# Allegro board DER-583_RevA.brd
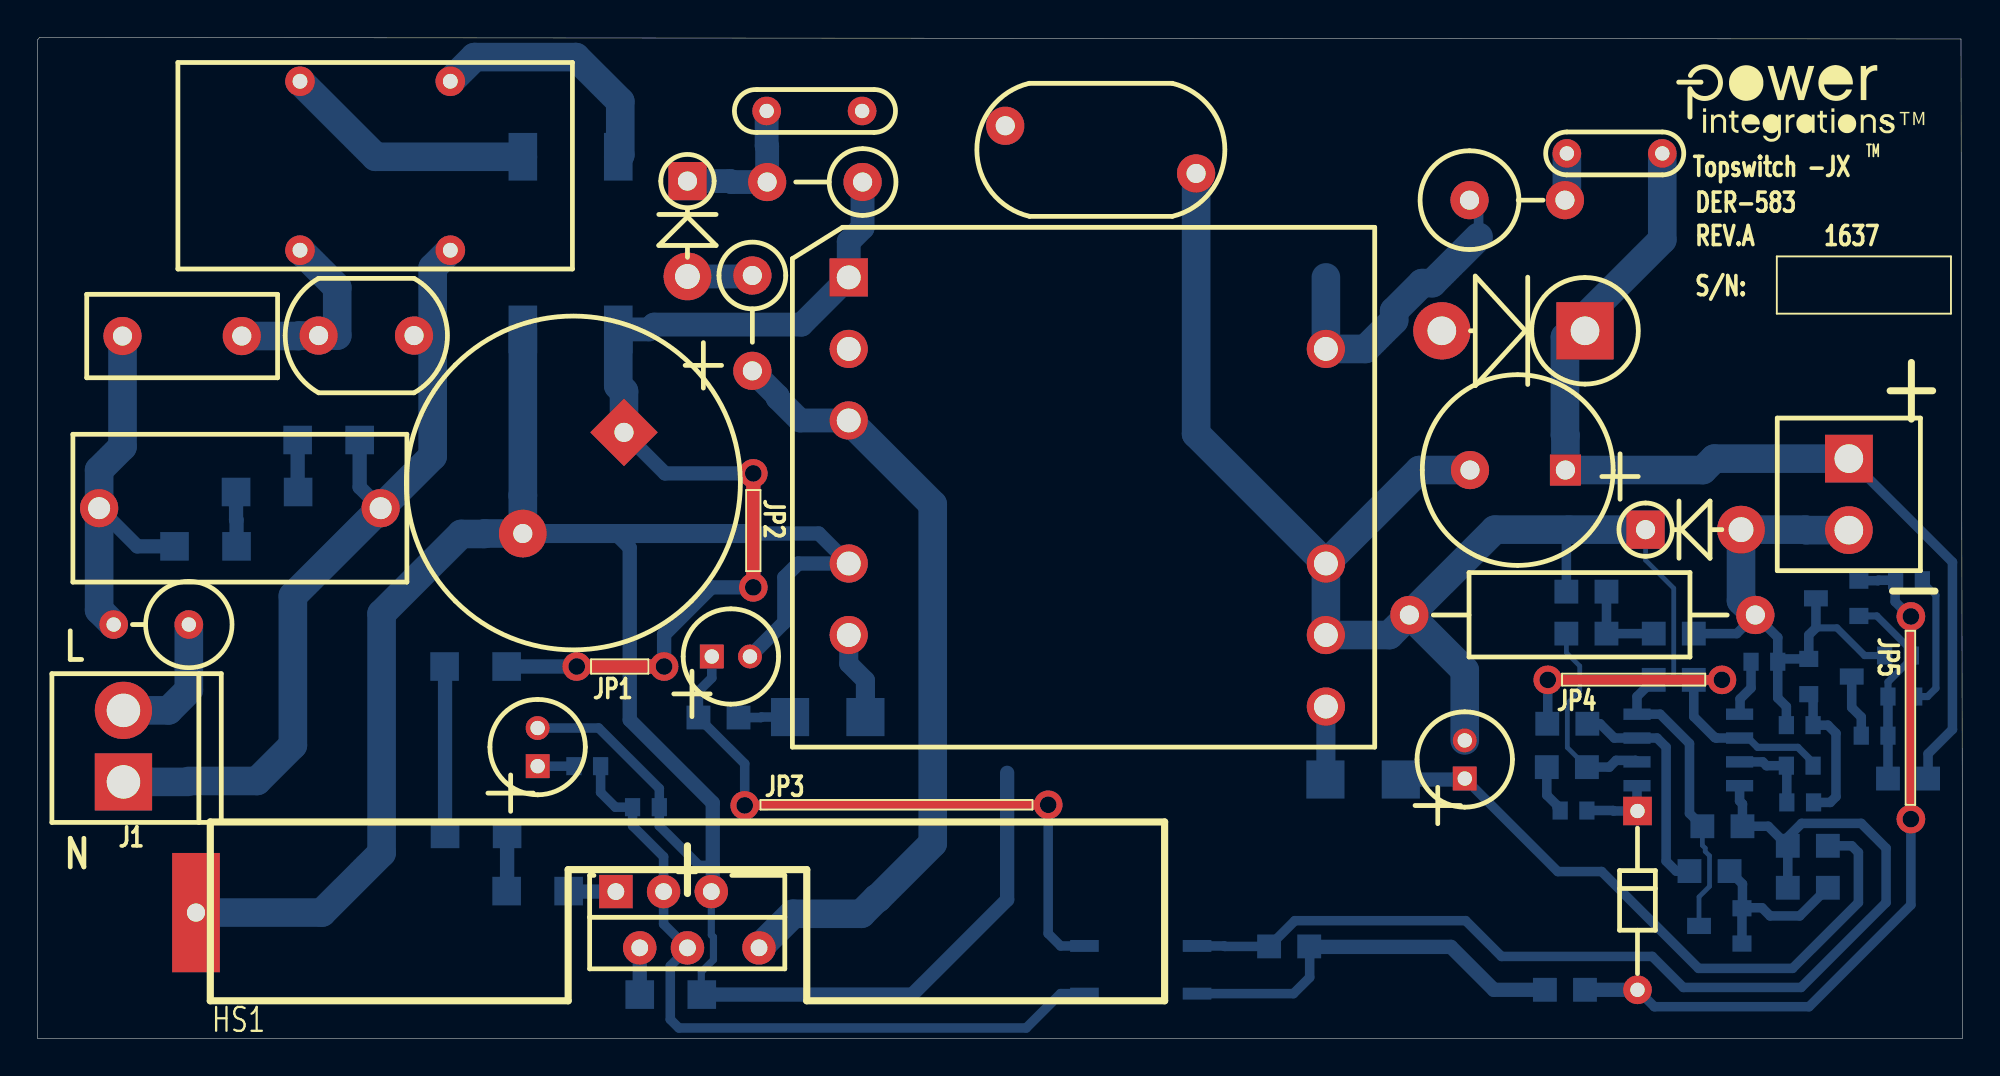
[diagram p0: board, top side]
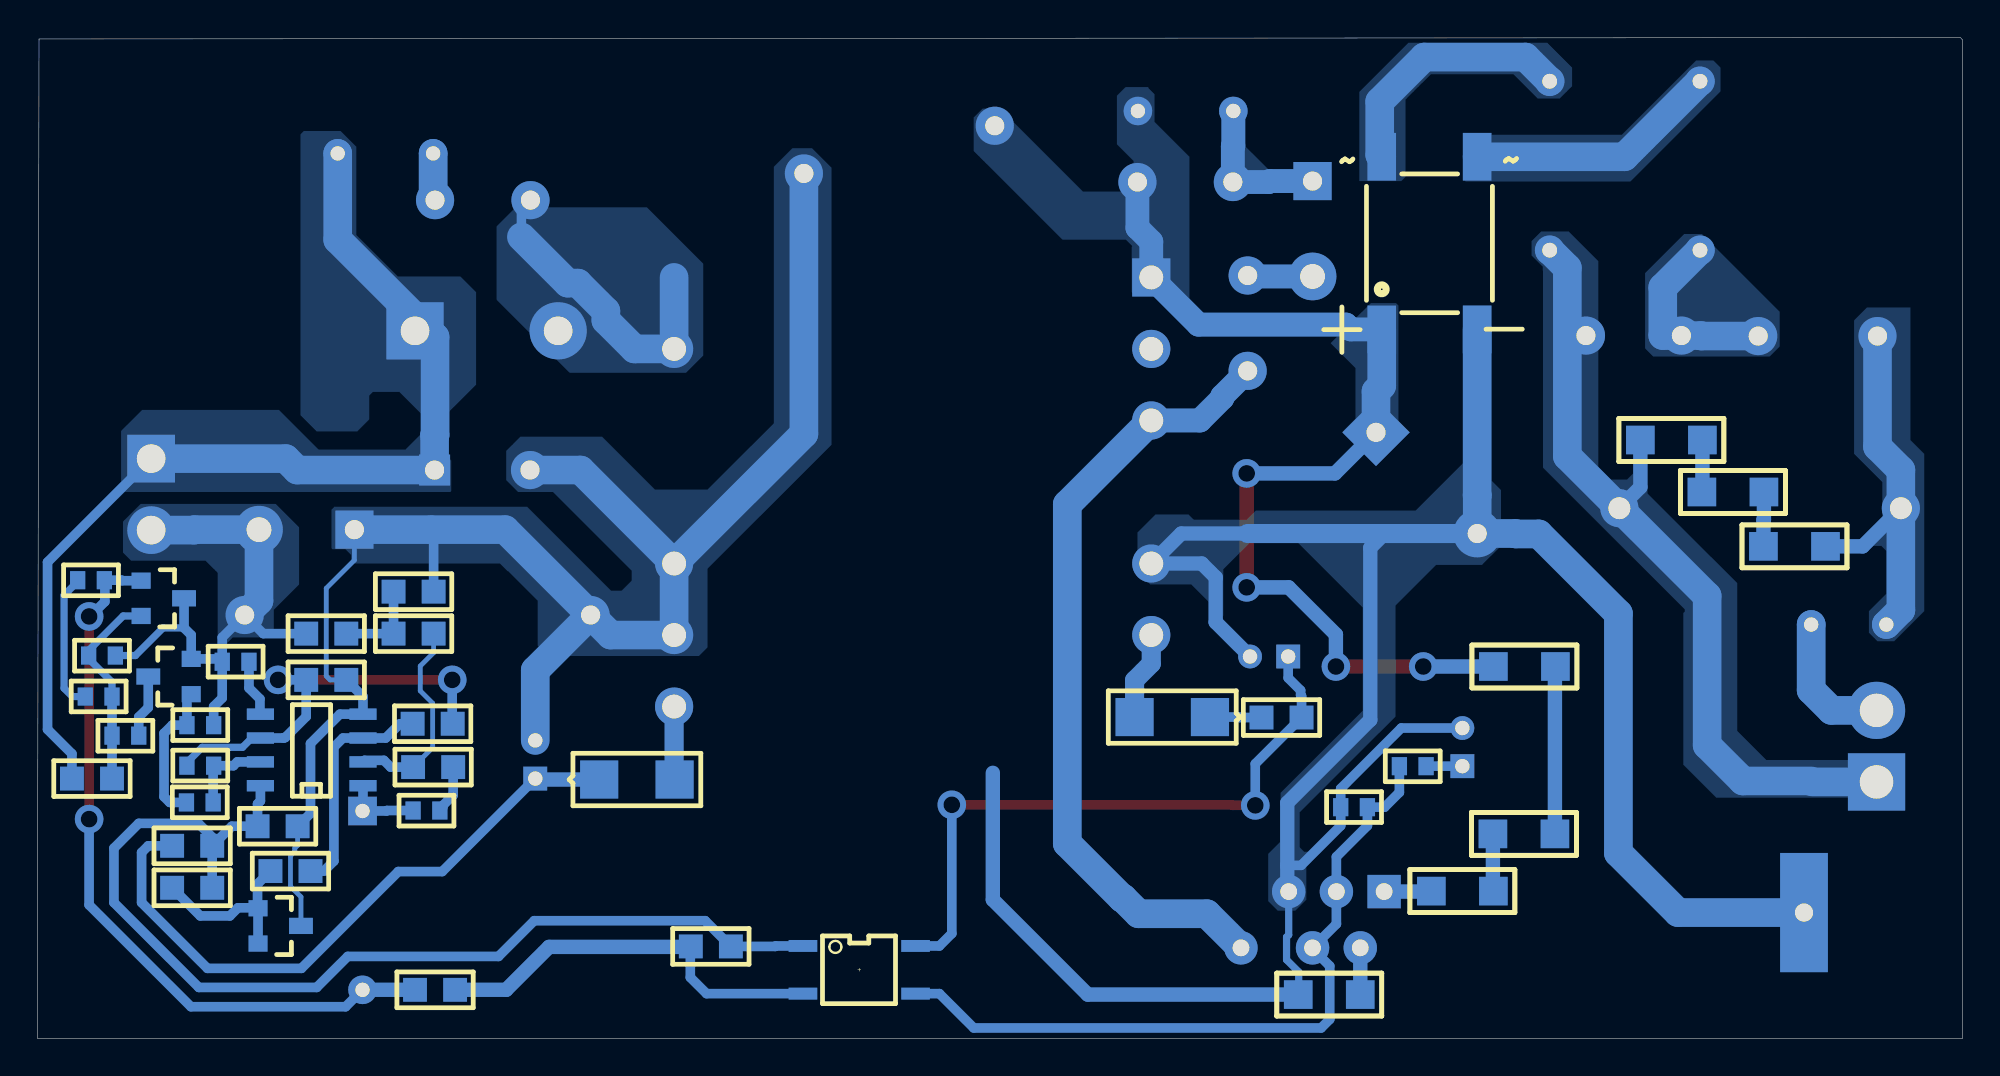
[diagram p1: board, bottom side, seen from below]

Outline 102.46 x 53.31 mm; copper layers: TOP, BOTTOM. Coordinates in mm from the lower left corner of the outline.
Outline path: 0,53.19 0.1,53.31 0.15,53.31 102.39,53.24 102.39,53.19 102.46,7.7 102.46,0 0,0 0,53.19

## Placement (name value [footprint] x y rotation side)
BR1  TBS20J-TP  [PISMD_4-TBS]  30.91 37.82 0 bottom
C1  330 nF  [PINPXCAPRAD710X315590046]  3.28 28.24 0 top
C2  82 uF  [PIPOLCAPCLYD710LS300040]  31.22 32.28 225 top
C3  2.2 nF  [PINPCAPRAD350X100200030]  38.81 49.4 0 top
C4  100 nF  [PISMC0603]  31.67 12.32 0 bottom
C5  47 uF  [PIPOLCAPCLYD200LS80030]  35.89 20.35 0 top
C6  47 uF  [PIPOLCAPCLYD200LS80030]  26.62 14.5 90 top
C7  2.2 nF  [PINPYCAPRAD540X290LS400040]  51.51 48.62 0 top
C8  220 uF  [PIPOLCAPCYLD400LS200040]  81.33 30.28 180 top
C9  220 pF  [PINPCAPRAD250X100200030]  81.41 47.14 0 top
C11  47 uF  [PIPOLCAPCLYD200LS80030]  75.97 13.84 90 top
C12  100 nF  [PISMC0603]  82.47 12.14 180 bottom
C13  100 nF  [PISMC0603]  98.5 18.21 0 bottom
C14  1 uF  [PISMC0805]  90.75 11.3 180 bottom
C15  47 nF  [PISMC0603]  93.09 14.53 0 bottom
C16  47 nF  [PISMC0805]  83.52 23.8 180 bottom
D1  FR107-B  [PIDV200X110X040DO41]  34.59 45.67 270 top
D2  US1D  [PISMDSMA]  40.06 17.12 0 bottom
D4  1N4148  [PIDV200X080X030DO35]  85.17 12.12 270 top
D6  1N4001  [PIDV200X110X040DO41]  85.6 27.1 0 top
D7  UF5404  [PIDV300X200X060DO15D0201AD]  82.37 37.69 180 top
D8  US1D  [PISMDSMA]  72.57 13.79 180 bottom
F1  2 A  [PIVAXIAL_D177_LS200_30]  8.05 22.05 180 top
HS1  HEATSINK, MACH, PI CUST, AL 6003  [PI_HS_DER569]  34.59 8.99 0 top
J1  CON2  [PI_HDR_2PIN_LS156_LCK]  4.55 13.72 180 top
J2  CON2  [PI_HDR_2PIN]  96.42 30.89 180 top
L2  9 mH  [PIIND4P827X433LS315X354031]  13.97 41.99 90 top
NOREF  -  []  -139.25 54.82 0 top
NOREF#2  -  []  102.46 0 90 top
NOREF#3  -  []  -217.07 -144.2 0 top
NOREF#4  -  []  87.25 52.32 0 top
NOREF#5  -  []  0 0 0 top
Q1  MMBT4401LT1G  [PISMSOT23123_1]  94.28 20.22 90 bottom
R1  680 k  [PISMR1206]  7.29 26.21 0 bottom
R2  680 k  [PISMR1206]  10.57 29.11 0 bottom
R3  680 k  [PISMR1206]  13.84 31.88 0 bottom
R4  33 k  [PI1WRESD200LS725D040]  43.92 45.62 180 top
R5  33  [PI1WRESD200LS725D040]  38.05 40.64 270 top
R6  3.30 M  [PISMR1206]  24.97 19.81 180 bottom
R7  3.30 M  [PISMR1206]  21.69 10.9 0 bottom
R8  2.00 M  [PISMR1206]  24.97 7.85 0 bottom
R9  6.65 k  [PISMR1206]  32.05 2.34 0 bottom
R10  6.8  [PISMR0603]  29.97 14.5 180 bottom
R11  68  [PI1WVRESD200LS200D040]  76.23 44.65 0 top
R12  470  [PISMR0805]  80.24 2.59 0 bottom
R13  8.87 k  [PISMR0805]  80.37 16.76 0 bottom
R14  0.15  [PI2WRESD200LS725D040]  73.03 22.56 0 top
R16  47  [PISMR0805]  95.3 10.26 180 bottom
R17  10 k  [PISMR0603]  100.33 24.41 180 bottom
R18  3.3 k  [PISMR0805]  80.34 14.45 0 bottom
R19  10 k  [PISMR0805]  81.38 21.56 0 bottom
R20  49.9 k  [PISMR0805]  100.63 13.84 180 bottom
R21  100 k  [PISMR0805]  90.07 8.92 180 bottom
R22  2.32 k  [PISMR0603]  99.75 20.4 180 bottom
R23  6.8 k  [PISMR0805]  95.3 8.03 180 bottom
R24  1 k  [PISMR0805]  65.56 4.9 0 bottom
R25  43.2 k  [PISMR0603]  98.5 16.13 180 bottom
R26  3.32 k  [PISMR0805]  86.03 19.1 0 bottom
R27  10 k  [PISMR0603]  93.12 12.57 0 bottom
R28  4.7 k  [PISMR0603]  91.21 20.07 0 bottom
R29  10 k  [PISMR0603]  93.09 16.69 0 bottom
R30  1  [PISMR0805]  35.18 17.09 0 bottom
R31  1 k  [PISMR0805]  86.03 21.56 0 bottom
RT1  5  [PIRAD400X175LS250040]  4.52 37.41 0 top
RV1  320 Vac  [PI_DISC_335X240LS200D040]  14.96 37.44 0 top
T1  PQ26/25  [PI_DER-569_XFRMR]  43.18 40.54 0 top
U1  TOP266EG  [PIICESIP76TH]  30.78 7.82 0 top
U2  PC357A  [PI_4_SMD]  58.72 3.66 270 bottom
U4  LM431BIM3/NOPB  [PISMSOT23123]  90.73 5.05 270 bottom
U5  LM358D  [PISMSO8]  85.14 13.46 90 bottom
U6  LM431BIM3/NOPB  [PISMSOT23123]  96.95 22.5 270 bottom

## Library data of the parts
BR1 = DIODE BRIDGE_+-~~
C1 C3 C4 C9 C12-C16 = CAP NP
C2 = CAP POL: alternate symbols: (pi_cap_cly_d710_ls300_040_1035h)
C5 C6 C11 = CAP POL: alternate symbols: (pipolcapclyd200ls80030l460h)
C7 = CAP NP: alternate symbols: (pinpycaprad540x290ls400040h)
C8 = CAP POL
D1 D6 = DIODE: alternate symbols: (pidax475x125040do41,pidv200x110x040do41wbead,pidax390x125040do41)
D2 D8 = DIODE
D4 = DIODE: alternate symbols: (pidax375x070030do35,pidv100x080x030do35)
D7 = DIODE: alternate symbols: (pidax800x225060do15do201ad,pidv300x200x060do14wbead)
F1 = FUSE: alternate symbols: (piaxiald_177ls787_30)
HS1 = HS-PI_CUSTOM1p
J1 J2 = CON2
L2 = INDUCTOR_4P_revG
Q1 = NPN_BEC
R1-R3 R6-R10 R12-R14 R16-R31 = R
R4 R5 R11 = R: alternate symbols: (pi1wvresd120ls200d040,pi1wvresd120ls300d040,pi1wvresd200ls200d040,pi1wvresd200ls300d040,pi1wvresd200ls350d040)
RT1 = THERMISTOR
RV1 = VARISTOR
T1 = DER-569_XFRMR
U1 = TOP26X_EG
U2 = OPTO_A_B
U4 U6 = TL431/SOT-23_CAR
U5 = LM358

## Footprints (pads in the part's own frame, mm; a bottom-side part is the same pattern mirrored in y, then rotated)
PI1WRESD200LS725D040
  round 2.032 hole 1.016: 1(0,0) 2(5.08,0)
PI1WVRESD200LS200D040
  round 2.032 hole 1.016: 1(0,0) 2(5.08,0)
PI2WRESD200LS725D040
  round 2.032 hole 1.016: 1(0,0) 2(18.415,0)
PI_4_SMD
  rect 0.635x1.524 smd: 1(-1.27,-2.997) 2(1.27,-2.997) 3(1.27,2.997) 4(-1.27,2.997)
PI_DER-569_XFRMR
  rect 2.032x2.032 hole 1.27: 1(0,0)
  round 2.032 hole 1.27: 2(0,-3.81) 3(0,-7.62) 4(0,-15.24) 5(0,-19.05) 7(25.4,-22.86) 8(25.4,-19.05) 9(25.4,-15.24) 11(25.4,-3.81)
PI_DISC_335X240LS200D040
  round 2.032 hole 1.016: 1(0,0) 2(5.08,0)
PI_HDR_2PIN
  rect 2.54x2.54 hole 1.524: 1(0,0)
  round 2.54 hole 1.524: 2(0,3.81)
PI_HDR_2PIN_LS156_LCK
  rect 3.048x3.048 hole 1.778: 1(-0.025,0.051)
  round 3.048 hole 1.778: 2(-0.025,-3.759)
PI_HS_DER569
  rect 2.54x6.35 hole 0.965: 1(-26.162,-2.286)
PIDV200X080X030DO35
  rect 1.524x1.524 hole 0.762: 1(0,0)
  round 1.524 hole 0.762: 2(9.525,0)
PIDV200X110X040DO41
  rect 2.032x2.032 hole 1.016: 1(0,0)
  round 2.54 hole 1.321: 2(5.08,0)
PIDV300X200X060DO15D0201AD
  rect 3.048x3.048 hole 1.524: 1(0,0)
  round 3.048 hole 1.524: 2(7.62,0)
PIICESIP76TH
  rect 1.778x1.778 hole 0.889: 1(0,0)
  round 1.778 hole 0.889: 2(1.27,-2.997) 3(2.54,0) 4(3.81,-2.997) 5(5.08,0) 7(7.62,-2.997)
PIIND4P827X433LS315X354031
  round 1.575 hole 0.787: 1(8.999,-8.001) 2(8.999,0) 3(0,0) 4(0,-8.001)
PINPCAPRAD250X100200030
  round 1.524 hole 0.762: 1(0,0) 2(5.08,0)
PINPCAPRAD350X100200030
  round 1.524 hole 0.762: 1(0,0) 2(5.08,0)
PINPXCAPRAD710X315590046
  round 2.032 hole 1.168: 1(0,0) 2(14.986,0)
PINPYCAPRAD540X290LS400040
  round 2.032 hole 1.016: 1(0,0) 2(10.16,-2.54)
PIPOLCAPCLYD200LS80030
  rect 1.27x1.27 hole 0.762: 1(0,0)
  round 1.27 hole 0.762: 2(2.032,0)
PIPOLCAPCLYD710LS300040
  rect 2.54x2.54 hole 1.016: 1(0,0)
  round 2.54 hole 1.016: 2(7.62,0)
PIPOLCAPCYLD400LS200040
  rect 1.651x1.651 hole 1.016: 1(0,0)
  round 2.032 hole 1.016: 2(5.08,0)
PIRAD400X175LS250040
  round 2.032 hole 1.016: 1(0,0) 2(6.35,0)
PISMC0603
  rect 0.813x0.965 smd: 1(0,0) 2(1.422,0)
PISMC0805
  rect 1.27x1.27 smd: 1(0,0) 2(2.134,0)
PISMD_4-TBS
  rect 1.524x2.54 smd: 1(0,0.051) 2(-5.08,0.051) 3(0,-9.144) 4(-5.08,-9.144)
PISMDSMA
  rect 2.032x2.032 smd: 1(0,0) 2(4.013,0)
PISMR0603
  rect 0.813x0.965 smd: 1(0,0) 2(1.422,0)
PISMR0805
  rect 1.27x1.27 smd: 1(0,0) 2(2.134,0)
PISMR1206
  rect 1.524x1.524 smd: 1(0,0) 2(3.302,0)
PISMSO8
  rect 0.61x1.448 smd: 1(0,0) 2(1.27,0) 3(2.54,0) 4(3.81,0) 5(3.81,5.461) 6(2.54,5.461) 7(1.27,5.461) 8(0,5.461)
PISMSOT23123
  rect 0.864x1.016 smd: 1(-1.88,0) 3(0,0)
  rect 0.864x1.27 smd: 2(-0.94,2.286)
PISMSOT23123_1
  rect 0.864x1.016 smd: 1(-1.88,0) 2(0,0)
  rect 0.864x1.27 smd: 3(-0.94,2.286)
PIVAXIAL_D177_LS200_30
  round 1.524 hole 0.762: 1(0,0) 2(4,0)

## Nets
N00906: C8.1 C9.2 D7.1 J2.1 R20.1
N01215: C7.2 C8.2 C11.2 C14.2 C16.2 D6.1 R14.1 R26.1 T1.8 T1.9 U4.2(A) U5.4(V-)
N01329: BR1.1 C2.1 C3.2 C7.1 R4.1 R6.1 T1.1
N01364: BR1.2 C2.2 C4.2 C5.2 C6.2 HS1.1 R9.2 T1.4 U1.5(S)
N01421: BR1.3 L2.1
N01764: L2.3 RT1.2 RV1.1
N01812: C1.2 J1.1 L2.4 R3.2 RV1.2
N01821: R2.2 R3.1
N01839: R1.2 R2.1
N02417: C1.1 F1.2 R1.1 RT1.1
N03024: R9.1 U1.2(X)
N03093: C4.1 R10.1 U1.3(C) U1.4(F) U2.3(E)
N03111: C6.1 R10.2
N03136: R8.2 U1.1(V)
N03143: R7.2 R8.1
N03168: R6.2 R7.1
N07742: D2.1 R30.2
N07860: C5.1 R30.1 U2.4(C)
N08806: D6.2 J2.2 Q1.2(EMITTER) R14.2 R22.2 R28.2 R29.1 R31.2 U6.2(A)
N09675: R18.2 R19.1 U5.2(-IN)
N09924: C13.1 R20.2 R22.1 R25.1 U6.3(VREF)
N16567: C3.1 D1.1 R4.2
N18059: F1.1 J1.2
N22833: R5.2 T1.3 U1.7(D)
N24164: R12.1 R24.2 U2.2(C)
N24263: C12.2 R18.1
N24295: C12.1 D4.1 U5.1(OUT)
N24455: D4.2 R12.2 R17.2 U6.1(C)
N26109: R21.1 R23.1 U4.1(C) U4.3(VREF)
N27634: R13.2 R21.2 U5.3(+IN)
N29605: C14.1 R16.2 R23.2 R24.1 U2.1(A) U5.8(V+)
N48309: D1.2 R5.1
N56239: BR1.4 L2.2
N77874: D7.2 R11.1 T1.11
N81445: C11.1 D8.1 R16.1
N82880: C15.2 R13.1 R26.2 U5.6(-IN)
N87772: C13.2 R17.1
N89028: C15.1 R27.1 U5.7(OUT)
N89032: Q1.1(BASE) R27.2 R29.2
N94097: C9.1 R11.2
N99851: R28.1 U5.5(+IN)
N104378: D8.2 T1.7
N110778: D2.2 T1.5
N118670: Q1.3(COLLECTOR) R25.2
N119358: C16.1 R19.2 R31.1

Pads without a net: T1 2

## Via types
v1: diameter 1.524, hole 0.889, TOP to BOTTOM, 10 vias

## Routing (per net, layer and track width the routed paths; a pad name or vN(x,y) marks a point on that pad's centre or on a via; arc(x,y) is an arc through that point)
N00906: length 54.2
  BOTTOM w0.508: R20.1 100.63,15.16 101.93,16.46 101.93,25.37 J2.1
  BOTTOM w1.524: J2.1 89.26,30.89 88.65,30.28 C8.1 81.33,32.12 81.31,32.14 81.31,37.36 86.49,42.55 C9.2
N01215: length 93.4
  BOTTOM w0.254: D6.1 85.6,25.48 87.1,23.98 87.1,19.3 86.89,19.1 R26.1 ; U4.2 88.44,7.54 89,8.1 89,9.73 88.77,9.96 88.77,10.13 88.62,10.29 C14.2
  BOTTOM w0.508: C14.2 87.93,11.99 87.93,15.71 86.37,17.27 U5.4 85.14,18.21 R26.1 ; C16.2 81.38,26.97 81.51,27.1
  BOTTOM w1.524: T1.9 73.56,30.28 C8.2 ; T1.9 T1.8 71.96,21.49 R14.1 ; T1.9 61.67,32.21 C7.2 ; D6.1 77.57,27.1 R14.1 ; R14.1 75.97,19.61 C11.2
N01329: length 54.4
  TOP w0.762: v1(33.35,19.81) v1(28.7,19.81) ; v1(38.1,30.1) v1(38.1,24.03)
  BOTTOM w0.762: C2.1 33.4,30.1 v1(38.1,30.1) ; v1(33.35,19.81) 33.35,21.51 35.86,24.03 v1(38.1,24.03) ; R6.1 v1(28.7,19.81)
  BOTTOM w1.27: R4.1 43.92,43.18 43.18,42.44 T1.1 40.67,38.02 32.82,38.02 32.56,37.77 BR1.1 31.11,37.97
  BOTTOM w1.524: BR1.1 30.91,34.77 31.22,34.47 C2.1
N01364: length 136.5
  BOTTOM w0.381: R9.2 35.33,2.36 35.33,3.54 35.98,4.19 35.98,5.4 35.86,5.51 U1.5
  BOTTOM w0.508: C6.2 29.87,16.54 33.1,13.31 C4.2 33.1,11.33 35.2,9.22 35.94,9.22
  BOTTOM w0.762: 51.61,14.15 51.61,7.39 46.56,2.34 R9.2 ; 38.05,26.9 41.58,26.9 T1.4 40.49,25.3 39.75,24.56 39.75,22.17 C5.2 ; 30.76,26.9 31.52,26.13 31.52,16.97 35.94,12.55 35.94,7.9 U1.5
  BOTTOM w1.016: 38.05,26.9 25.83,26.9
  BOTTOM w1.524: BR1.2 25.83,28.93 25.83,28.93 25.83,26.9 23.8,26.9 23.77,26.87 22.56,26.87 18.31,22.63 18.31,9.88 15.14,6.71 HS1.1
N01421: length 13.5
  BOTTOM w1.524: L2.1 23.26,52.27 28.65,52.27 31.02,49.91 31.02,47.07 BR1.3
N01764: length 10.5
  BOTTOM w1.524: L2.3 15.95,40.01 15.95,37.44 RV1.1 13.92,37.44 13.89,37.41 RT1.2
N01812: length 43.8
  BOTTOM w0.762: R3.2 17.14,29.36 C1.2 ; 8.05,13.72 8,13.67
  BOTTOM w1.524: L2.4 21.03,41.05 21.03,31.01 C1.2 13.59,23.57 13.59,15.62 11.68,13.72 8.05,13.72 ; 8,13.67 J1.1
N01821: length 2.8
  BOTTOM w0.762: R2.2 13.84,29.13 R3.1
N01839: length 2.9
  BOTTOM w0.762: R2.1 10.57,27.64 10.59,27.61 R1.2
N02417: length 21.1
  BOTTOM w0.762: R1.1 5.31,26.21 C1.1
  BOTTOM w1.524: F1.2 3.28,22.82 C1.1 3.28,30.28 4.52,31.52 RT1.1
N03024: length 2.5
  BOTTOM w0.762: U1.2 R9.1
N03093: length 39.3
  BOTTOM w0.508: R10.1 29.97,13.11 30.76,12.32 C4.1 31.67,11.33 33.32,9.68 U1.3 33.32,6.1 U1.4 34.59,4.78 33.68,3.86 33.68,1.02 34.14,0.56 52.63,0.56 54.46,2.39 U2.3
N03111: length 1.9
  BOTTOM w0.508: C6.1 R10.2
N03136: length 2.5
  BOTTOM w0.762: R8.2 28.3,7.82 U1.1
N03143: length 3.1
  BOTTOM w0.762: R7.2 24.99,7.87 R8.1
N03168: length 8.9
  BOTTOM w0.762: R6.2 21.69,19.79 R7.1
N07742: length 2.8
  BOTTOM w0.508: D2.1 38.53,17.12 38.51,17.09 R30.2
N07860: length 34.5
  TOP w0.508: v1(37.64,12.42) 38.84,12.42 38.87,12.45 v1(53.8,12.45)
  BOTTOM w0.508: v1(37.64,12.42) 37.64,14.63 R30.1 35.18,18.24 35.23,18.29 35.23,18.54 35.89,19.2 C5.1 ; v1(53.8,12.45) 53.8,5.59 54.46,4.93 U2.4
N08806: length 30.2
  BOTTOM w0.381: 94.67,21.87 95.78,21.87 97.26,20.4 R22.2
  BOTTOM w0.508: R31.2 90.45,21.56 R14.2 92.63,21.36 R28.2 ; R28.2 92.79,20.22 Q1.2 94.28,21.49 94.67,21.87 U6.2 ; R28.2 92.63,18.14 93.09,17.68 R29.1
  BOTTOM w1.524: J2.2 94.13,27.08 94.11,27.1 D6.2 90.68,23.32 R14.2
N09675: length 11
  BOTTOM w0.254: R18.2 81.43,15.49 81.43,17.86 82.09,18.52 82.09,19.84 81.38,20.55 R19.1 81.38,21.59
  BOTTOM w0.508: R18.2 83.67,14.45 84.03,14.81 85.06,14.81 U5.2
N09924: length 10.9
  BOTTOM w0.381: C13.1 98.5,18.98 99.75,20.23 R22.1 99.75,20.67 97.91,22.5 U6.3
  BOTTOM w0.508: 98.5,13.79 R20.2 R25.1 C13.1
N16567: length 8.1
  BOTTOM w1.27: C3.1 38.81,47.55 38.84,47.52 R4.2 36.93,45.62 36.88,45.67 D1.1
N18059: length 7.4
  BOTTOM w1.524: J1.2 6.97,17.48 8.05,18.55 F1.1
N22833: length 42.2
  BOTTOM w1.27: R5.2 39.4,34.21 39.4,34.11 40.59,32.92 T1.3
  BOTTOM w1.524: T1.3 47.65,28.45 47.65,10.39 44.73,7.47 44.68,7.47 43.85,6.64 40.22,6.64 U1.7
N24164: length 21.6
  BOTTOM w0.508: U2.2 66.85,2.39 67.72,3.25 67.72,4.88 R24.2
  BOTTOM w0.762: R12.1 77.52,2.59 75.23,4.88 67.61,4.88
N24263: length 2.6
  BOTTOM w0.508: R18.1 80.34,12.96 80.9,12.4 80.9,12.29 C12.2
N24295: length 4.1
  BOTTOM w0.508: U5.1 85.14,12.14 D4.1 83.9,12.12 83.87,12.14 C12.1
N24455: length 39.6
  TOP w0.508: v1(99.72,22.48) v1(99.72,11.68)
  BOTTOM w0.508: D4.2 86.07,1.69 94.3,1.69 99.72,7.11 v1(99.72,11.68) ; v1(99.72,22.48) 99.67,22.48 98.88,23.27 98.88,24.38 R17.2 97.99,24.41 97.97,24.38 U6.1
  BOTTOM w0.762: R12.2 D4.2
N26109: length 9.6
  BOTTOM w0.508: 90.75,6.96 90.75,8.23 R21.1 90.04,8.94 ; 90.75,6.96 91.8,6.96 92.23,6.53 93.8,6.53 R23.1 95.33,8.05 ; 90.75,6.96 U4.1 U4.3
N27634: length 12.2
  BOTTOM w0.508: R13.2 83.17,16.76 83.93,16 U5.3 86.21,16 86.69,15.52 86.69,9.45 87.22,8.92 R21.2
N29605: length 57.4
  BOTTOM w0.508: R16.2 93.17,10.72 93.9,11.46 97.08,11.46 98.4,10.13 98.4,7.24 93.88,2.72 87.6,2.72 85.95,4.37 77.93,4.37 76.02,6.27 66.93,6.27 R24.1 63.2,4.9 63.17,4.93 U2.1 ; R16.2 92.13,11.3 C14.1 90.75,12.5 90.6,12.65 U5.8 ; R16.2 R23.2 93.17,8
N48309: length 3.5
  BOTTOM w1.27: R5.1 38,40.59 D1.2
N56239: length 13.5
  BOTTOM w1.524: BR1.4 17.99,46.96 L2.2
N77874: length 16.9
  BOTTOM w0.508: 76.71,42.7 76.71,44.17 R11.1
  BOTTOM w1.524: 76.71,42.7 74.24,40.23 73.7,40.23 72.21,38.75 72.21,38.25 70.69,36.73 T1.11 68.58,40.54
N81445: length 34.5
  BOTTOM w0.508: C11.1 80.92,8.89 83.26,8.89 88.42,3.73 93.42,3.73 96.93,7.24 96.93,9.91 96.57,10.26 R16.1
  BOTTOM w0.762: D8.1 75.92,13.79 C11.1
N82880: length 22.6
  TOP w0.508: v1(89.66,19.1) v1(80.39,19.1)
  BOTTOM w0.381: U5.6 91.06,16 91.56,15.51 93.7,15.51 94.51,14.7 C15.2
  BOTTOM w0.508: v1(89.66,19.1) R26.2 88.16,17.14 89.28,16.03 89.34,16.03 89.37,16 U5.6 ; R13.1 80.39,16.79 v1(80.39,19.1)
N87772: length 7.4
  BOTTOM w0.381: R17.1 100.33,24.33 101.05,23.61 101.05,18.66 100.61,18.21 C13.2 99.9,18.21
N89028: length 4.6
  BOTTOM w0.508: C15.1 92.04,14.53 91.83,14.73 U5.7 ; C15.1 93.12,14.53 ; C15.1 93.12,14.5 R27.1
N89032: length 7.8
  BOTTOM w0.508: R27.2 95.43,12.57 95.73,12.88 95.73,16.26 95.3,16.69 R29.2 94.51,18.11 Q1.1
N94097: length 2.5
  BOTTOM w1.524: R11.2 81.41,44.75 C9.1
N99851: length 3
  BOTTOM w0.508: R28.1 91.21,18.67 90.63,18.08 90.63,17.3 U5.5
N104378: length 3.9
  BOTTOM w1.016: T1.7 68.58,13.82 D8.2
N110778: length 4.7
  BOTTOM w1.016: T1.5 43.18,19.96 44.07,19.08 D2.2
N118670: length 3.4
  BOTTOM w0.508: Q1.3 96.57,17.63 97.08,17.12 R25.2
N119358: length 4.7
  BOTTOM w0.508: C16.1 R19.2 R31.1

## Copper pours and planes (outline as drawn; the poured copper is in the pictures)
N00906 on BOTTOM: 79.12,39.75 79.12,34.82 81.15,32.79 81.56,32.79 83.21,34.44 84.61,34.44 84.81,34.24 84.81,32.97 85.45,32.33 87.6,32.33 88.47,33.2 88.47,48.16 88.29,48.34 86.33,48.34 85.5,47.5 85.5,42.8 83.29,40.59 79.96,40.59
N00906 on BOTTOM: 81.86,32.21 82.04,32.21 82.88,31.37 87.5,31.37 89.61,33.48 96.9,33.48 98.02,32.36 98.02,29.13 97.99,29.11 80.49,29.11 80.44,29.16 80.44,30.78
N01215 on BOTTOM: 76.76,32.05 72.42,32.05 69.6,29.24 66.8,29.24 63.27,32.77 63.27,46.43 62.28,47.42 61.24,47.42 60.2,46.38 60.2,31.62 66.8,25.02 66.8,20.83 67.26,20.37 75.29,20.37 75.84,20.93 75.84,23.32 77.42,24.89 77.44,24.89 77.85,25.3 85.78,25.3 85.78,25.76 86.08,26.06 86.77,26.06 86.82,26.11 86.82,28.17 86.66,28.32 76.4,28.32 71.93,23.85 71.37,23.85 70.84,24.38 70.84,24.92 75.03,29.11 76.89,29.11 77.52,29.74 77.52,31.29
N01329 on BOTTOM: 33.66,37.01 33.6,37.01 32.31,35.71 32.31,32.99 32.92,32.38 32.87,32.33 30.02,32.33 30.02,39.04 30.15,39.17 31.5,39.17
N01329 on BOTTOM: 52.65,47.29 47.9,42.55 44.53,42.55 44.18,42.2 44.22,42.16 44.22,39.75 44.09,39.62 41.94,39.62 41.33,39.01 41.17,39.01 41.15,39.04 41.15,46.96 43,48.82 43,50.29 43.33,50.62 43.33,50.67 44.55,50.67 45.01,50.22 45.01,47.62 44.12,46.74 44.12,45.62 44.63,45.11 46.81,45.11 51.23,49.53 52.14,49.53 52.15,49.54 52.63,49.05 52.63,47.32
N01364 on BOTTOM: 26.31,30.96 26.31,30.91 29.11,28.12 37.62,28.12 38.11,27.62 38.13,27.64 40.92,27.64 41.2,27.91 42.95,27.91 43.92,26.95 43.92,24.87 43.23,24.18 41.05,24.18 39.37,22.5 39.34,22.53 39.34,24.99 37.83,26.5 35.47,26.5 31.93,22.96 31.93,17.45 36.3,13.08 36.3,10.49 36.96,9.83 36.96,7.32 36.45,6.81 35.51,6.81 34.92,7.39 34.92,9.14 34.14,9.93 34.14,9.94 35.04,9.94 35.28,10.19 35.28,12.04 30.18,17.14 30.18,23.06 28.02,25.22 25.58,25.22 24.56,26.24 24.56,29.21
N01421 on BOTTOM: 20.78,50.72 20.78,51.71 22.1,53.04 29.49,53.04 32.11,50.42 32.11,45.67 29.87,45.67 29.64,45.9 29.64,50.01 28.3,51.36 23.9,51.36 22.61,50.06 21.44,50.06
N01764 on BOTTOM: 14.81,42.85 13.87,42.85 9.73,38.71 9.73,36.86 10.26,36.32 16.46,36.32 16.89,36.75 16.89,40.77
N01812 on BOTTOM: 20.97,42.99 19.38,41.4 19.38,30.43 18.72,29.77 17.86,29.77 16.76,30.86 16.76,29.03 11.99,24.26 11.99,16.38 10.44,14.83 5.84,14.83 5.79,14.78 5.79,13.06 6.02,12.83 13.11,12.83 14.86,14.58 14.86,22.66 14.78,22.73 14.78,22.86 22.33,30.4 22.33,40.89 22.34,40.91 22.34,41.11 22.94,41.71 22.94,42.47 22.42,42.99
N02417 on BOTTOM: 2.77,38.94 2.77,31.88 2.03,31.14 2.03,22.76 3.63,21.16 4.52,21.16 4.98,21.62 4.98,22.76 4.04,23.7 4.04,25.96 4.32,26.24 4.78,26.24 5,26.47 5,26.77 4.27,27.51 4.27,29.64 5.77,31.14 5.77,38.25 5.08,38.94
N08806 on BOTTOM: 96.98,28.47 89.79,28.47 88.54,27.23 88.54,24.18 89.89,22.83 89.89,21.39 89.9,21.37 90.4,21.37 90.41,21.36 92.08,21.36 92.76,20.68 92.88,20.79 92.88,24.8 93.52,25.45 97.49,25.45 97.92,25.88 97.92,27.53
N16567 on BOTTOM: 38.73,48.08 36.3,45.64 36.35,45.59 39.01,45.59 39.01,47.8
N56239 on BOTTOM: 12.88,50.44 17.68,45.64 26.44,45.64 26.54,45.75 26.54,47.5 25.91,48.13 18.14,48.13 14.17,52.1 13.26,52.1 12.88,51.71
N77874 on BOTTOM: 77.01,44.27 70.03,44.27 67.03,41.27 67.03,36.37 67.94,35.46 74.14,35.46 78.03,39.34 78.03,43.26

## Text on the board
Ref Des/Silkscreen Top: TM | JP1 | JP3 | JP4 | Topswitch -JX | DER-583 | REV.A | S/N: | 1637 | JP2 | JP5 | L | N | + | -
PEN17: 14.  FAB HOUSE LOGO,DATE CODE TO BE IN SILK SCREEN ONLY.DO NOT USE COPPER. | 13.  MATERIAL FR4 COPPER 2oz THICKNESS 0.062" | 1 Slot
User.5: FIGURE | SIZE | 30.0 | 31.0 | 35.0 | 38.0 | 40.0 | 46.0 | 50.0 | 52.0 | 60.0 | 70.0 | DRILL CHART: TOP to BOTTOM | ALL UNITS ARE IN MILS | PLATED | QTY | 14 | 4 | 6 | 10 | 1 | 20 | 2 | 12
